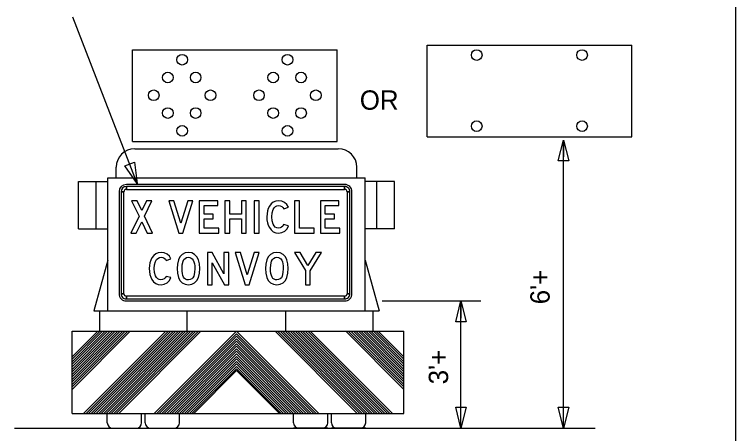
# Model space of a CAD drawing. Extents: x 1373848 to 1374003, y 380642 to 381248.
# Drawn here: x 1373932.11 to 1373954.48, y 381030.08 to 381043.07 of the extents above; entities that cross this region are included whole.
import ezdxf

# ---------------------------------------------------------------- set-up
doc = ezdxf.new("R2010")
doc.units = 0
doc.layers.add('Working Level 1', color=7, linetype='Continuous')

msp = doc.modelspace()

# ---------------------------------------------------------------- linework, layer by layer
at = {"layer": 'Working Level 1'}
for p, q in [((1373954.481, 381081.277), (1373954.481, 380977.045)), ((1373935.924, 381037.829), (1373933.922, 381042.984)), ((1373944.917, 381039.278), (1373944.917, 381042.122)), ((1373944.917, 381042.122), (1373951.26, 381042.122)), ((1373951.26, 381039.278), (1373951.26, 381042.122)), ((1373935.779, 381041.976), (1373942.122, 381041.976)), ((1373935.779, 381039.132), (1373935.779, 381041.976)), ((1373942.122, 381039.132), (1373942.122, 381041.976)), ((1373935.779, 381039.132), (1373942.122, 381039.132)), ((1373944.917, 381039.278), (1373951.26, 381039.278)), ((1373949.144, 381030.244), (1373949.144, 381039.176)), ((1373949.144, 381039.176), (1373949.144, 381038.652)), ((1373935.844, 381038.908), (1373942.158, 381038.908)), ((1373935.27, 381038.005), (1373935.27, 381038.334)), ((1373942.732, 381038.005), (1373942.732, 381038.334)), ((1373935.01, 381033.878), (1373935.01, 381038.005)), ((1373935.01, 381038.005), (1373942.992, 381038.005)), ((1373942.992, 381033.878), (1373942.992, 381038.005)), ((1373934.099, 381036.421), (1373934.099, 381037.888)), ((1373934.099, 381037.888), (1373935.01, 381037.888)), ((1373934.651, 381036.421), (1373934.651, 381037.888)), ((1373942.355, 381037.798), (1373935.584, 381037.798)), ((1373943.903, 381037.888), (1373942.992, 381037.888)), ((1373943.352, 381036.421), (1373943.352, 381037.888)), ((1373943.903, 381036.421), (1373943.903, 381037.888)), ((1373935.358, 381037.572), (1373935.358, 381034.412)), ((1373935.421, 381037.572), (1373935.509, 381037.572)), ((1373935.584, 381037.647), (1373935.584, 381037.735)), ((1373942.355, 381037.735), (1373942.355, 381037.647)), ((1373942.431, 381037.572), (1373942.519, 381037.572)), ((1373942.581, 381034.412), (1373942.581, 381037.572)), ((1373934.099, 381036.421), (1373935.01, 381036.421)), ((1373943.903, 381036.421), (1373942.992, 381036.421)), ((1373935.01, 381035.45), (1373934.578, 381033.878)), ((1373942.992, 381035.45), (1373943.424, 381033.878)), ((1373935.509, 381034.412), (1373935.421, 381034.412)), ((1373942.519, 381034.412), (1373942.431, 381034.412)), ((1373935.584, 381034.249), (1373935.584, 381034.337)), ((1373942.355, 381034.337), (1373942.355, 381034.249)), ((1373935.584, 381034.186), (1373942.355, 381034.186)), ((1373943.519, 381034.186), (1373946.58, 381034.186)), ((1373945.963, 381030.244), (1373945.963, 381034.186)), ((1373945.963, 381034.186), (1373945.963, 381033.654)), ((1373934.578, 381033.878), (1373943.424, 381033.878)), ((1373934.757, 381033.248), (1373934.757, 381033.878)), ((1373937.469, 381033.248), (1373937.469, 381033.867)), ((1373940.533, 381033.248), (1373940.533, 381033.867)), ((1373943.245, 381033.248), (1373943.245, 381033.878)), ((1373933.9, 381033.248), (1373944.195, 381033.248)), ((1373933.9, 381033.248), (1373944.195, 381033.248)), ((1373933.9, 381033.248), (1373944.195, 381033.248)), ((1373933.9, 381033.248), (1373944.195, 381033.248)), ((1373933.9, 381030.698), (1373933.9, 381033.248)), ((1373933.9, 381032.45), (1373934.698, 381033.248)), ((1373933.9, 381031.522), (1373935.626, 381033.248)), ((1373933.9, 381031.6), (1373935.548, 381033.248)), ((1373933.9, 381031.678), (1373935.47, 381033.248)), ((1373933.9, 381031.755), (1373935.393, 381033.248)), ((1373933.9, 381031.833), (1373935.315, 381033.248)), ((1373933.9, 381031.911), (1373935.237, 381033.248)), ((1373933.9, 381031.988), (1373935.16, 381033.248)), ((1373933.9, 381032.066), (1373935.082, 381033.248)), ((1373933.9, 381032.145), (1373935.004, 381033.248)), ((1373933.9, 381032.223), (1373934.926, 381033.248)), ((1373933.9, 381032.3), (1373934.849, 381033.248)), ((1373933.9, 381032.378), (1373934.77, 381033.248)), ((1373933.9, 381031.444), (1373935.702, 381033.246)), ((1373934.26, 381030.698), (1373936.809, 381033.248)), ((1373934.337, 381030.698), (1373936.887, 381033.248)), ((1373934.415, 381030.698), (1373936.965, 381033.248)), ((1373934.493, 381030.698), (1373937.043, 381033.248)), ((1373934.57, 381030.698), (1373937.12, 381033.248)), ((1373934.648, 381030.698), (1373937.198, 381033.248)), ((1373934.726, 381030.698), (1373937.276, 381033.248)), ((1373934.805, 381030.698), (1373937.354, 381033.248)), ((1373934.882, 381030.698), (1373937.431, 381033.248)), ((1373934.96, 381030.698), (1373937.509, 381033.248)), ((1373935.038, 381030.698), (1373937.588, 381033.248)), ((1373935.115, 381030.698), (1373937.665, 381033.248)), ((1373935.193, 381030.698), (1373937.743, 381033.248)), ((1373935.271, 381030.698), (1373937.82, 381033.247)), ((1373935.349, 381030.698), (1373937.898, 381033.248)), ((1373936.451, 381030.698), (1373939.001, 381033.248)), ((1373936.529, 381030.698), (1373939.001, 381033.17)), ((1373936.607, 381030.698), (1373939.001, 381033.092)), ((1373941.551, 381030.698), (1373939.001, 381033.248)), ((1373941.469, 381030.702), (1373939.001, 381033.17)), ((1373941.396, 381030.698), (1373939.001, 381033.092)), ((1373942.747, 381030.698), (1373940.197, 381033.248)), ((1373942.825, 381030.698), (1373940.276, 381033.247)), ((1373942.903, 381030.698), (1373940.353, 381033.248)), ((1373942.981, 381030.698), (1373940.431, 381033.248)), ((1373943.058, 381030.698), (1373940.508, 381033.248)), ((1373943.136, 381030.698), (1373940.586, 381033.248)), ((1373943.214, 381030.698), (1373940.664, 381033.248)), ((1373943.291, 381030.698), (1373940.741, 381033.248)), ((1373943.369, 381030.698), (1373940.819, 381033.248)), ((1373943.447, 381030.698), (1373940.897, 381033.248)), ((1373943.525, 381030.698), (1373940.976, 381033.248)), ((1373943.602, 381030.698), (1373941.053, 381033.248)), ((1373943.68, 381030.698), (1373941.131, 381033.248)), ((1373943.759, 381030.698), (1373941.209, 381033.248)), ((1373943.836, 381030.698), (1373941.286, 381033.248)), ((1373944.195, 381031.444), (1373942.394, 381033.246)), ((1373944.195, 381031.522), (1373942.469, 381033.248)), ((1373944.195, 381031.6), (1373942.547, 381033.248)), ((1373944.195, 381031.678), (1373942.626, 381033.248)), ((1373944.195, 381031.755), (1373942.703, 381033.248)), ((1373944.195, 381031.833), (1373942.781, 381033.248)), ((1373944.195, 381031.911), (1373942.859, 381033.248)), ((1373944.195, 381031.988), (1373942.936, 381033.248)), ((1373944.195, 381032.066), (1373943.014, 381033.248)), ((1373944.195, 381032.145), (1373943.092, 381033.248)), ((1373944.195, 381032.223), (1373943.17, 381033.248)), ((1373944.195, 381032.3), (1373943.247, 381033.248)), ((1373944.195, 381032.378), (1373943.325, 381033.248)), ((1373944.195, 381032.45), (1373943.397, 381033.248)), ((1373944.195, 381030.698), (1373944.195, 381033.248)), ((1373936.685, 381030.698), (1373939.001, 381033.014)), ((1373936.762, 381030.698), (1373939.001, 381032.937)), ((1373936.84, 381030.698), (1373939.001, 381032.859)), ((1373941.318, 381030.698), (1373939.001, 381033.014)), ((1373941.241, 381030.698), (1373939.001, 381032.937)), ((1373941.163, 381030.698), (1373939.001, 381032.859)), ((1373936.918, 381030.698), (1373939.001, 381032.781)), ((1373936.995, 381030.698), (1373939.001, 381032.704)), ((1373937.073, 381030.698), (1373939.001, 381032.626)), ((1373941.084, 381030.698), (1373939.001, 381032.781)), ((1373941.007, 381030.698), (1373939.001, 381032.704)), ((1373940.929, 381030.698), (1373939.001, 381032.626)), ((1373937.151, 381030.698), (1373939.001, 381032.548)), ((1373937.23, 381030.698), (1373939.001, 381032.47)), ((1373940.851, 381030.698), (1373939.001, 381032.548)), ((1373940.773, 381030.698), (1373939.001, 381032.47)), ((1373937.307, 381030.698), (1373939.001, 381032.393)), ((1373937.385, 381030.698), (1373939.001, 381032.315)), ((1373937.463, 381030.698), (1373939.001, 381032.236)), ((1373940.696, 381030.698), (1373939.001, 381032.393)), ((1373940.618, 381030.698), (1373939.001, 381032.315)), ((1373940.54, 381030.698), (1373939.001, 381032.236)), ((1373937.54, 381030.698), (1373939.001, 381032.159)), ((1373937.617, 381030.698), (1373939.001, 381032.082)), ((1373937.683, 381030.713), (1373939.001, 381032.031)), ((1373940.463, 381030.698), (1373939.001, 381032.159)), ((1373940.385, 381030.698), (1373939.001, 381032.082)), ((1373940.334, 381030.698), (1373939.001, 381032.031)), ((1373933.9, 381030.698), (1373944.195, 381030.698)), ((1373933.9, 381030.698), (1373944.195, 381030.698)), ((1373933.9, 381030.698), (1373944.195, 381030.698)), ((1373933.9, 381030.698), (1373944.195, 381030.698)), ((1373934.994, 381030.409), (1373934.994, 381030.698)), ((1373936.058, 381030.409), (1373936.058, 381030.698)), ((1373936.168, 381030.409), (1373936.168, 381030.698)), ((1373937.232, 381030.409), (1373937.232, 381030.698)), ((1373940.77, 381030.409), (1373940.77, 381030.698)), ((1373941.834, 381030.409), (1373941.834, 381030.698)), ((1373941.944, 381030.409), (1373941.944, 381030.698)), ((1373943.008, 381030.409), (1373943.008, 381030.698)), ((1373932.112, 381030.244), (1373950.124, 381030.244)), ((1373934.994, 381030.244), (1373936.058, 381030.244)), ((1373934.994, 381030.244), (1373936.058, 381030.244)), ((1373934.994, 381030.244), (1373936.058, 381030.244)), ((1373934.994, 381030.244), (1373936.058, 381030.244)), ((1373936.168, 381030.244), (1373937.232, 381030.244)), ((1373936.168, 381030.244), (1373937.232, 381030.244)), ((1373936.168, 381030.244), (1373937.232, 381030.244)), ((1373936.168, 381030.244), (1373937.232, 381030.244)), ((1373941.834, 381030.244), (1373940.77, 381030.244)), ((1373941.834, 381030.244), (1373940.77, 381030.244)), ((1373941.834, 381030.244), (1373940.77, 381030.244)), ((1373941.834, 381030.244), (1373940.77, 381030.244)), ((1373943.008, 381030.244), (1373941.944, 381030.244)), ((1373943.008, 381030.244), (1373941.944, 381030.244)), ((1373943.008, 381030.244), (1373941.944, 381030.244)), ((1373943.008, 381030.244), (1373941.944, 381030.244))]:
    msp.add_line(p, q, dxfattribs=at)
for points in [[(1373948.982, 381038.526), (1373949.144, 381039.176), (1373949.307, 381038.526)], [(1373935.84, 381038.494), (1373935.924, 381037.829), (1373935.537, 381038.376)], [(1373935.421, 381037.572), (1373935.421, 381034.412), (1373935.509, 381034.412), (1373935.509, 381037.572), (1373935.421, 381037.572)], [(1373942.355, 381037.735), (1373935.584, 381037.735), (1373935.584, 381037.647), (1373942.355, 381037.647), (1373942.355, 381037.735)], [(1373942.519, 381034.412), (1373942.519, 381037.572), (1373942.431, 381037.572), (1373942.431, 381034.412), (1373942.519, 381034.412)], [(1373936.395, 381036.293), (1373936.145, 381036.818), (1373936.374, 381037.296), (1373936.206, 381037.296), (1373936.061, 381036.993), (1373935.916, 381037.296), (1373935.748, 381037.296), (1373935.977, 381036.817), (1373935.725, 381036.293), (1373935.893, 381036.293), (1373936.06, 381036.642), (1373936.227, 381036.293)], [(1373937.648, 381037.296), (1373937.489, 381037.296), (1373937.274, 381036.603), (1373937.059, 381037.296), (1373936.901, 381037.296), (1373937.211, 381036.293), (1373937.336, 381036.293)], [(1373938.448, 381036.444), (1373937.993, 381036.444), (1373937.993, 381036.728), (1373938.276, 381036.728), (1373938.276, 381036.88), (1373937.993, 381036.88), (1373937.993, 381037.145), (1373938.417, 381037.145), (1373938.417, 381037.296), (1373937.841, 381037.296), (1373937.841, 381036.293), (1373938.448, 381036.293)], [(1373939.303, 381036.293), (1373939.303, 381037.296), (1373939.152, 381037.296), (1373939.152, 381036.88), (1373938.792, 381036.88), (1373938.792, 381037.296), (1373938.641, 381037.296), (1373938.641, 381036.293), (1373938.792, 381036.293), (1373938.792, 381036.728), (1373939.152, 381036.728), (1373939.152, 381036.293)], [(1373939.701, 381036.293), (1373939.701, 381037.296), (1373939.55, 381037.296), (1373939.55, 381036.293)], [(1373940.611, 381036.516), (1373940.459, 381036.554), (1373940.437, 381036.51), (1373940.4, 381036.475), (1373940.353, 381036.452), (1373940.301, 381036.444), (1373940.248, 381036.452), (1373940.203, 381036.476), (1373940.165, 381036.516), (1373940.134, 381036.572), (1373940.103, 381036.675), (1373940.093, 381036.794), (1373940.103, 381036.914), (1373940.135, 381037.018), (1373940.167, 381037.073), (1373940.206, 381037.113), (1373940.252, 381037.137), (1373940.306, 381037.145), (1373940.356, 381037.137), (1373940.402, 381037.117), (1373940.44, 381037.084), (1373940.466, 381037.042), (1373940.611, 381037.099), (1373940.562, 381037.179), (1373940.491, 381037.242), (1373940.404, 381037.282), (1373940.308, 381037.296), (1373940.22, 381037.285), (1373940.143, 381037.254), (1373940.077, 381037.202), (1373940.022, 381037.129), (1373939.987, 381037.056), (1373939.962, 381036.977), (1373939.947, 381036.889), (1373939.942, 381036.795), (1373939.946, 381036.701), (1373939.961, 381036.614), (1373939.986, 381036.534), (1373940.022, 381036.462), (1373940.075, 381036.388), (1373940.14, 381036.335), (1373940.216, 381036.303), (1373940.303, 381036.293), (1373940.405, 381036.308), (1373940.497, 381036.355), (1373940.569, 381036.426)], [(1373941.41, 381036.293), (1373941.41, 381036.444), (1373940.955, 381036.444), (1373940.955, 381037.296), (1373940.804, 381037.296), (1373940.804, 381036.293)], [(1373942.21, 381036.444), (1373941.755, 381036.444), (1373941.755, 381036.728), (1373942.039, 381036.728), (1373942.039, 381036.88), (1373941.755, 381036.88), (1373941.755, 381037.145), (1373942.179, 381037.145), (1373942.179, 381037.296), (1373941.603, 381037.296), (1373941.603, 381036.293), (1373942.21, 381036.293)], [(1373936.967, 381034.91), (1373936.815, 381034.949), (1373936.793, 381034.905), (1373936.756, 381034.87), (1373936.709, 381034.847), (1373936.657, 381034.839), (1373936.604, 381034.847), (1373936.559, 381034.871), (1373936.52, 381034.911), (1373936.49, 381034.967), (1373936.459, 381035.07), (1373936.449, 381035.189), (1373936.459, 381035.309), (1373936.491, 381035.413), (1373936.523, 381035.468), (1373936.562, 381035.508), (1373936.608, 381035.532), (1373936.662, 381035.54), (1373936.712, 381035.532), (1373936.757, 381035.512), (1373936.795, 381035.479), (1373936.821, 381035.437), (1373936.967, 381035.494), (1373936.918, 381035.574), (1373936.846, 381035.637), (1373936.759, 381035.677), (1373936.664, 381035.691), (1373936.575, 381035.68), (1373936.499, 381035.649), (1373936.433, 381035.597), (1373936.378, 381035.524), (1373936.342, 381035.451), (1373936.317, 381035.372), (1373936.302, 381035.284), (1373936.297, 381035.19), (1373936.302, 381035.096), (1373936.317, 381035.009), (1373936.342, 381034.929), (1373936.377, 381034.857), (1373936.431, 381034.783), (1373936.496, 381034.73), (1373936.572, 381034.698), (1373936.659, 381034.688), (1373936.761, 381034.703), (1373936.853, 381034.75), (1373936.924, 381034.821)], [(1373937.86, 381035.19), (1373937.849, 381035.333), (1373937.819, 381035.467), (1373937.774, 381035.558), (1373937.702, 381035.629), (1373937.611, 381035.675), (1373937.509, 381035.691), (1373937.407, 381035.675), (1373937.317, 381035.629), (1373937.245, 381035.557), (1373937.2, 381035.466), (1373937.169, 381035.332), (1373937.159, 381035.19), (1373937.169, 381035.048), (1373937.2, 381034.913), (1373937.245, 381034.822), (1373937.317, 381034.75), (1373937.407, 381034.703), (1373937.509, 381034.688), (1373937.611, 381034.703), (1373937.701, 381034.75), (1373937.773, 381034.821), (1373937.818, 381034.912), (1373937.849, 381035.046)], [(1373937.708, 381035.189), (1373937.699, 381035.067), (1373937.673, 381034.954), (1373937.648, 381034.907), (1373937.611, 381034.87), (1373937.564, 381034.847), (1373937.51, 381034.839), (1373937.463, 381034.844), (1373937.423, 381034.861), (1373937.388, 381034.888), (1373937.36, 381034.927), (1373937.339, 381034.976), (1373937.323, 381035.036), (1373937.314, 381035.107), (1373937.311, 381035.189), (1373937.32, 381035.311), (1373937.346, 381035.424), (1373937.37, 381035.471), (1373937.408, 381035.508), (1373937.455, 381035.532), (1373937.51, 381035.54), (1373937.556, 381035.534), (1373937.596, 381035.518), (1373937.63, 381035.49), (1373937.658, 381035.452), (1373937.68, 381035.403), (1373937.696, 381035.343), (1373937.705, 381035.271)], [(1373938.762, 381034.688), (1373938.762, 381035.691), (1373938.611, 381035.691), (1373938.611, 381035.031), (1373938.245, 381035.691), (1373938.1, 381035.691), (1373938.1, 381034.688), (1373938.251, 381034.688), (1373938.251, 381035.368), (1373938.629, 381034.688)], [(1373939.709, 381035.691), (1373939.551, 381035.691), (1373939.335, 381034.998), (1373939.12, 381035.691), (1373938.962, 381035.691), (1373939.273, 381034.688), (1373939.397, 381034.688)], [(1373940.603, 381035.19), (1373940.592, 381035.333), (1373940.562, 381035.467), (1373940.517, 381035.558), (1373940.445, 381035.629), (1373940.354, 381035.675), (1373940.252, 381035.691), (1373940.15, 381035.675), (1373940.06, 381035.629), (1373939.988, 381035.557), (1373939.943, 381035.466), (1373939.913, 381035.332), (1373939.902, 381035.19), (1373939.913, 381035.048), (1373939.943, 381034.913), (1373939.988, 381034.822), (1373940.06, 381034.75), (1373940.15, 381034.703), (1373940.252, 381034.688), (1373940.354, 381034.703), (1373940.444, 381034.75), (1373940.516, 381034.821), (1373940.561, 381034.912), (1373940.592, 381035.046)], [(1373940.451, 381035.189), (1373940.442, 381035.067), (1373940.416, 381034.954), (1373940.392, 381034.907), (1373940.354, 381034.87), (1373940.307, 381034.847), (1373940.253, 381034.839), (1373940.206, 381034.844), (1373940.166, 381034.861), (1373940.131, 381034.888), (1373940.104, 381034.927), (1373940.082, 381034.976), (1373940.066, 381035.036), (1373940.057, 381035.107), (1373940.054, 381035.189), (1373940.063, 381035.311), (1373940.089, 381035.424), (1373940.113, 381035.471), (1373940.151, 381035.508), (1373940.198, 381035.532), (1373940.253, 381035.54), (1373940.299, 381035.534), (1373940.34, 381035.518), (1373940.374, 381035.49), (1373940.402, 381035.452), (1373940.423, 381035.403), (1373940.439, 381035.343), (1373940.448, 381035.271)], [(1373941.637, 381035.691), (1373941.459, 381035.691), (1373941.213, 381035.29), (1373940.972, 381035.691), (1373940.796, 381035.691), (1373941.137, 381035.127), (1373941.137, 381034.688), (1373941.288, 381034.688), (1373941.288, 381035.123)], [(1373935.584, 381034.249), (1373942.355, 381034.249), (1373942.355, 381034.337), (1373935.584, 381034.337), (1373935.584, 381034.249)], [(1373945.801, 381033.536), (1373945.963, 381034.186), (1373946.126, 381033.536)], [(1373946.126, 381030.894), (1373945.963, 381030.244), (1373945.801, 381030.894)], [(1373949.307, 381030.894), (1373949.144, 381030.244), (1373948.982, 381030.894)]]:
    msp.add_lwpolyline(points, close=True, dxfattribs=at)
for centre in [(1373937.314, 381041.666), (1373940.581, 381041.666), (1373946.452, 381041.811), (1373949.72, 381041.811), (1373936.873, 381041.114), (1373937.734, 381041.114), (1373940.14, 381041.114), (1373941.002, 381041.114), (1373936.432, 381040.563), (1373938.195, 381040.563), (1373939.699, 381040.563), (1373941.463, 381040.563), (1373936.873, 381040.012), (1373937.734, 381040.012), (1373940.14, 381040.012), (1373941.002, 381040.012), (1373937.314, 381039.461), (1373940.581, 381039.461), (1373946.452, 381039.606), (1373949.72, 381039.606)]:
    msp.add_circle(centre, 0.165, dxfattribs=at)
for centre, radius, start, end in [((1373935.844, 381038.334), 0.574, 90, 180), ((1373942.158, 381038.334), 0.574, 0, 90), ((1373935.584, 381037.572), 0.226, 90.0002, 179.9998), ((1373942.355, 381037.572), 0.226, 0, 90.0002), ((1373935.584, 381037.572), 0.163, 90.0002, 179.9998), ((1373935.584, 381037.572), 0.0752, 90.0002, 179.9998), ((1373942.355, 381037.572), 0.163, 0, 90.0002), ((1373942.355, 381037.572), 0.0752, 0, 90.0002), ((1373935.584, 381034.412), 0.226, 179.9998, 270.0001), ((1373935.584, 381034.412), 0.163, 179.9998, 270.0001), ((1373935.584, 381034.412), 0.0752, 179.9998, 270.0001), ((1373942.355, 381034.412), 0.226, 270.0001, 0.0003), ((1373942.355, 381034.412), 0.163, 270.0001, 0.0003), ((1373942.355, 381034.412), 0.0752, 270.0001, 0.0003), ((1373935.159, 381030.409), 0.165, 180, 270), ((1373935.893, 381030.409), 0.165, 270, 0), ((1373936.333, 381030.409), 0.165, 180, 270), ((1373937.067, 381030.409), 0.165, 270, 0), ((1373940.935, 381030.409), 0.165, 180, 270), ((1373941.669, 381030.409), 0.165, 270, 0), ((1373942.109, 381030.409), 0.165, 180, 270), ((1373942.843, 381030.409), 0.165, 270, 0)]:
    msp.add_arc(centre, radius, start, end, dxfattribs=at)

# ---------------------------------------------------------------- texts
msp.add_text('OR', height=0.6, dxfattribs=at).set_placement((1373942.825, 381040.115))
for s, p in [("6'+", (1373948.714, 381034.084)), ("3'+", (1373945.564, 381031.603))]:
    msp.add_text(s, height=0.6, rotation=90, dxfattribs=at).set_placement(p)

doc.saveas('drawing.dxf')
